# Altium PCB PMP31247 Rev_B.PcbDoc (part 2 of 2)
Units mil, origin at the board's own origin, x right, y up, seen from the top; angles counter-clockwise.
Board outline 3522.83 x 1490.94 mil, 4 copper layers (Top Layer, GND Plane, Signal Layer, Bottom Layer), stack 70.4 mil thick; 56 components, 24 nets, 121 pads, 112 vias.
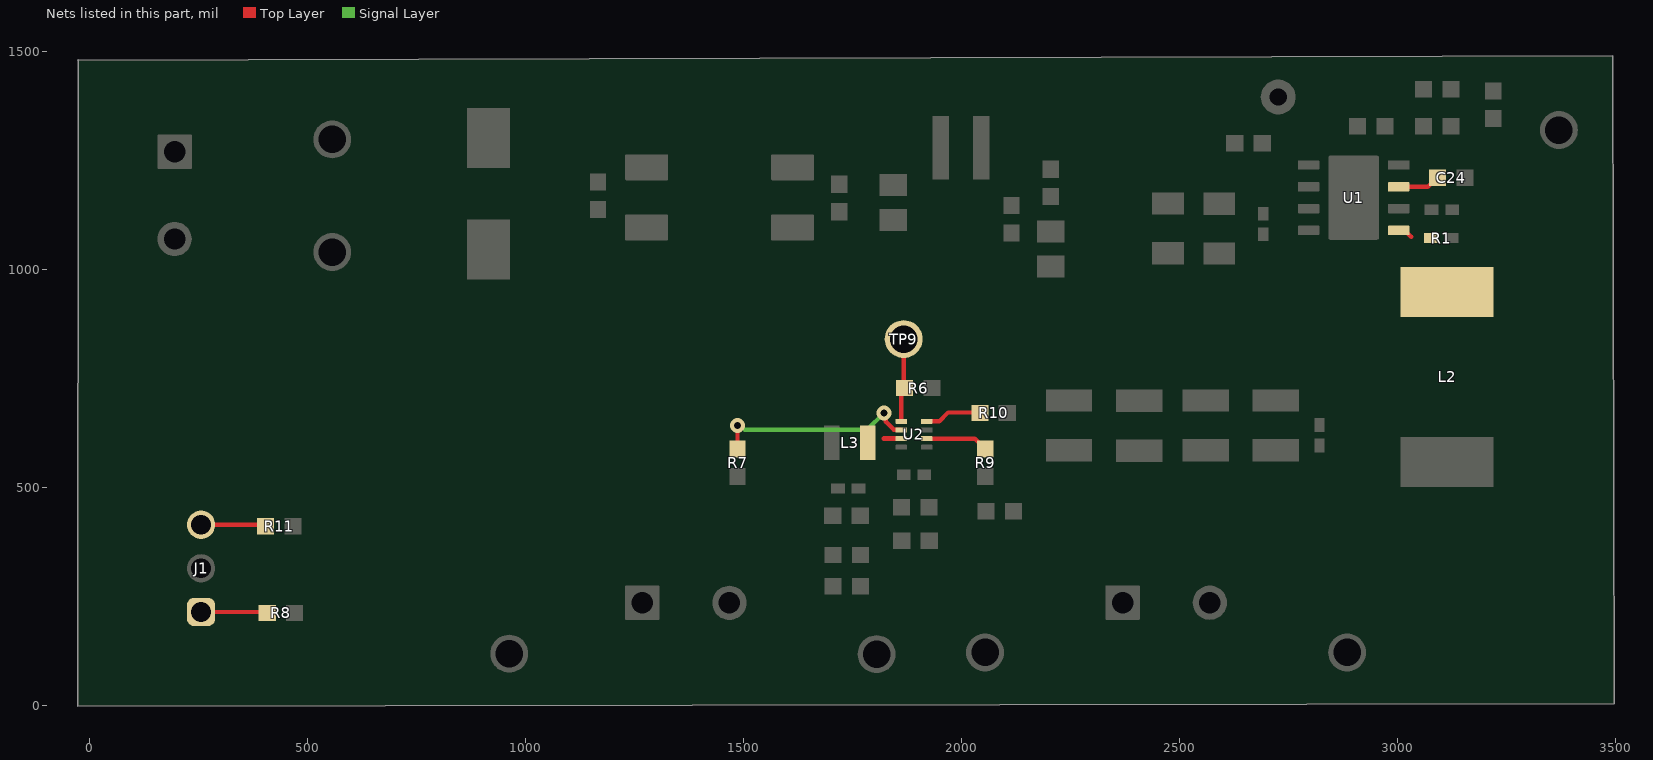
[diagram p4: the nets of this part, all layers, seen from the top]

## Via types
v1: diameter 34, hole 16, Top Layer to Bottom Layer, tented both sides, 104 vias
v2: diameter 19.68, hole 7.87, Top Layer to Bottom Layer, 4 vias
v3: diameter 19.68, hole 7.87, Top Layer to Bottom Layer, tented both sides, 4 vias

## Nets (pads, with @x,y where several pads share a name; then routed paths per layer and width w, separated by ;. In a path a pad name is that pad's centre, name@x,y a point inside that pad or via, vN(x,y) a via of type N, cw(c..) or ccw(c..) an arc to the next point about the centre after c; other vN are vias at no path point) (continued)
NetJ1_1: J1.1 R8.1 | length 166.9
  Top Layer w10: J1.1@255.91,214.96 R8.1@405.51,214.96 ; R8.1@395.28,212.2 R8.1@407.48,224.41
NetJ1_3: J1.3 R11.2 | length 143.3
  Top Layer w10: J1.3@255.91,414.96 R11.2@399.21,414.96
NetL2_1: L2.1 R1.1 U1.1 | length 141.2
  Top Layer w10: U1.1@3001.97,1089.76 3015.75,1089.76 3030.71,1074.8 ; L2.1@3032.08,1000.91 3084.17,948.82 L2.1@3112.79,948.82 ; R1.1@3071.85,1072.27 R1.1@3075.79,1072.27
NetL3_1: L3.1 U2.7 | length 45.6
  Top Layer w10: L3.1@1792.38,623.42 L3.1@1796.4,619.41 ; 1821.49,612.35 1821.59,612.44
  Top Layer w11.81: 1821.59,612.44 U2.7@1861.42,612.44
NetR6_1: R6.1 TP9.1 U2.5 | length 179.7
  Top Layer w10: U2.5@1861.42,651.81 R6.1@1861.42,718.5 ; TP9.1@1866.96,840.55 1866.96,730.28 R6.1@1868.9,728.35
NetR7_1: R7.1 U2.6 | length 474.3
  Top Layer w10: R7.1@1486.02,588.8 v1(1486.02,642.31) ; v1(1821.59,671.26) 1826.18,666.67 1826.18,650.89 1844.04,633.03 1860.51,633.03 U2.6@1861.42,632.13
  Signal Layer w10: v1(1486.02,642.31) 1492.52,642.31 1502.16,632.68 1783,632.68 v1(1821.59,671.26)
NetR9_2: R9.2 U2.2 | length 144.7
  Top Layer w10: U2.2@1919.69,612.44 2030.08,612.44 2039.25,603.27 2040.24,603.27 2053.94,589.57 R9.2@2053.94,588.58
NetR10_2: R10.2 U2.4 | length 130.7
  Top Layer w10: U2.4@1919.69,651.81 1948.35,651.81 1968.73,672.19 2040.61,672.19 R10.2@2041.54,671.26
VCC: C24.1 U1.3 | length 97.2
  Top Layer w10: U1.3@3001.97,1189.76 3002.17,1189.96 3068.9,1189.96 3089.57,1210.63 C24.1@3090.55,1210.63
pads on no net: U1.9@2898.62,1164.76

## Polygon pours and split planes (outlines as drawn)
GND on Top Layer "GND_L01_P058" (solid, remove dead copper, pour order 63): 1.97,774.8 3643.7,774.8 3643.7,-395.67 3639.76,-391.73 1.97,-391.73
NetC2_1 on Top Layer "NETC2_1_L01_P066" (solid, remove dead copper, pour order 66): 2024.82,1204.72 2024.82,1353.54 2024.94,1353.66 2065.9,1353.66 2065.9,1353.41 2104.91,1314.4 2104.91,1204.72
NetC6_1 on Top Layer "NETC6_1_L01_P065" (solid, remove dead copper, pour order 65): 1971.65,1204.72 1971.65,1353.54 1971.54,1353.66 1930.58,1353.66 1930.58,1353.41 1895.67,1318.5 1895.67,1204.72
NetC14_1 on Top Layer "NETC14_1_L01_P040" (solid, remove dead copper, pour order 40): 2075.34,464.41 2074.81,464.94 1970.89,464.94 1937.8,498.03 1894.01,498.03 1894.01,356.78 1894.49,356.3 1894.5,356.31 1965.08,356.31 2035.93,427.17 2075.56,427.17
NetL3_1 on Top Layer "NETL3_1_L01_P046" (solid, remove dead copper, pour order 46): 1835.53,615.97 1835.53,606.77 ccw(c1835.53,591.58) 1824.79,602.32 1801.84,563.95 1767.98,582.75 1767.98,616.53
NetL3_1 on Top Layer "NETL3_1_L01_P064" (solid, remove dead copper, pour order 64): 1834.28,609.05 1834.28,618.25 cw(c1834.27,633.44) 1823.54,622.7 1801.93,642.63 1766.73,641.02 1766.73,608.48
NetL2_1 on Top Layer "NETL2_1_L01_P049" (solid, remove dead copper, pour order 49): 2977.49,1101.41 3081.37,1101.41 cw(c3074.22,1080.95) 3093.74,1090.36 3093.74,1018.76 ccw(c3119.99,1045) 3119.99,1007.88 3212.65,1007.88 cw(c3212.65,993.39) 3222.89,1003.64 cw(c3220.37,1001.12) 3223.94,1001.12 3223.94,894.69 cw(c3215.19,894.68) 3221.38,888.5 3218.5,885.63 cw(c3211.29,892.84) 3211.29,882.64 3020.61,882.64 cw(c3020.61,906.92) 3003.44,889.75 cw(c3007.01,893.32) 3001.97,893.32 3001.97,1069.33 ccw(c2980.58,1047.4) 2981.67,1078.01 2977.49,1078.01
NetC2_1 on Top Layer "NETC2_1_L01_P050" (solid, remove dead copper, pour order 50): 2071.3,1319.88 2297.28,1319.88 2407.27,1209.9 2712.85,1209.9 2773.5,1149.25 2817.93,1149.25 2817.93,1127.95 2812.97,1122.99 2344.4,1122.99 2257.49,1209.9 2071.3,1209.9
GNDA on Top Layer "GNDA_L01_P051" (solid, remove dead copper, pour order 51): 1326.77,1125.98 1326.77,1066.93 1153.15,893.31 17.32,893.31 17.32,1125.98
NetC5_1 on Top Layer "NETC5_1_L01_P052" (solid, remove dead copper, pour order 52): 1326.77,1204.72 1326.77,1263.78 1137.8,1452.76 16.14,1452.76 16.14,1204.72
3V3 on Top Layer "3V3_L01_P053" (solid, remove dead copper, pour order 53): 2184.29,616.14 3188.98,616.14 3188.98,498.03 2791.34,498.03 2720.47,427.17 2184.29,427.17
NetC14_1 on Top Layer "NETC14_1_L01_P054" (solid, remove dead copper, pour order 54): 1937.8,356.3 1937.8,600.39 1906.3,600.39 1906.3,549.21 1894.49,537.4 1894.49,356.3
Net1.2V_1 on Top Layer "NET1.2V_1_L01_P055" (solid, remove dead copper, pour order 55): 1735.7,642.31 1735.7,258.53 1595.28,118.11 1376.77,118.11 1376.77,390 1539.49,390 1683.97,534.48 1683.97,642.31
3V3 on Top Layer "3V3_L01_P056" (solid, remove dead copper, pour order 56): 2272.44,444.91 2272.44,161.42 2278.35,155.51 2473.23,155.51 2473.23,425.43 2477.17,444.91
GND on Top Layer "GND_L01_P057" (solid, remove dead copper, pour order 57): 1562.99,1126.38 1564.54,1124.83 1726.62,1124.83 1726.62,1068.08 1561.02,1068.08
GND on Top Layer "GND_L01_P058" (solid, remove dead copper, pour order 58): 1563.64,1124.83 1753.28,1124.83 1775.91,1102.2 2116.93,1102.2 2116.93,1090.36 2173.83,1033.46 2246.06,1033.46 2322.83,1033.46 2322.83,907.48 2114.89,907.48 2049.93,972.44 1731.3,972.44 1577.27,1070.11
NetC6_1 on Top Layer "NETC6_1_L01_P059" (solid, remove dead copper, pour order 59): 1567.87,1204.72 1925.57,1204.72 1925.57,1319.88 1652.95,1319.88 1597.96,1264.89 1567.87,1264.89
GND on Top Layer "GND_L01_P061" (solid, remove dead copper, pour order 61): 2316.93,1623.36 2316.93,676.91 3638.05,676.91 3643.7,671.26 3643.7,1631.89
GND on GND Plane "GND_L02_P021" (solid, remove dead copper, pour order 21): 2316.93,1623.36 2316.93,676.91 3638.05,676.91 3643.7,671.26 3643.7,1631.89
GND on GND Plane "GND_L02_P020" (solid, remove dead copper, pour order 20): 2.79,775.1 3644.53,775.1 3644.53,-394.85 3640.59,-390.91 2.79,-390.91
GND on Signal Layer "GND_L03_P027" (solid, remove dead copper, pour order 27): 2316.93,1615.48 2316.93,669.04 3638.05,669.04 3643.7,663.39 3643.7,1624.02
GND on Signal Layer "GND_L03_P028" (solid, remove dead copper, pour order 28): 0.32,775.1 3642.06,775.1 3642.06,-395.67 3638.12,-391.73 0.32,-391.73
GND on Bottom Layer "GND_L04_P030" (solid, remove dead copper, pour order 30): 1.97,775.1 3643.7,775.1 3643.7,-395.67 3639.76,-391.73 1.97,-391.73
GND on Bottom Layer "GND_L04_P029" (solid, remove dead copper, pour order 29): 2316.93,1623.36 2316.93,676.91 3638.05,676.91 3643.7,671.26 3643.7,1631.89

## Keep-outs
Keep-Out Layer:
  text ".Layer_Name" at 572.5,-1392.79 h60

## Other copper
Top Layer:
  pour cut-out: -5.17,770.02 -7.48,767.72 -7.48,512.99 1273.62,512.99 1535.43,774.8
  text ".Layer_Name" at 493.76,-1392.79 h60
GND Plane:
  pour cut-out: -7.48,770.31 -7.48,513.29 1273.37,513.29 1535.18,775.1
  text ".Layer_Name" at 572.5,-1394.76 h60
Signal Layer:
  pour cut-out: 13.13,770.38 -3.15,754.09 -3.15,513.29 1273.76,513.29 1535.57,775.1
  text ".Layer_Name" at 573.29,-1392.79 h60
Bottom Layer:
  pour cut-out: 13.13,770.38 -0.79,756.46 -0.79,513.29 1273.76,513.29 1535.57,775.1
  text ".Layer_Name" at 572.5,-1392.79 h60

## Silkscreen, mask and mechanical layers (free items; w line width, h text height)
Top Overlay:
  text "GND" at 142.22,903.64 h30
  text "'.PRJ_Number' Rev_B" at 272.05,580.31 h108.27
  text "PFM" at 72.93,397.34 h30
  text "SYNC" at 69.39,301.28 h30
  text "FPWM" at 73.32,198.91 h30
  text ".Layer_Name" at 572.5,-1392.79 h60
Bottom Overlay:
  text ".Layer_Name" at 572.5,-1392.79 h60
Top Paste:
  text ".Layer_Name" at 572.5,-1392.79 h60
Bottom Paste:
  text ".Layer_Name" at 572.5,-1392.79 h60
Top Solder:
  text ".Layer_Name" at 572.5,-1392.79 h60
  text ".Layer_Name" at 572.5,-1392.79 h60
Bottom Solder:
  text ".Layer_Name" at 572.5,-1392.79 h60
Drill Guide:
  text ".Layer_Name" at 572.5,-1392.79 h60
M1 Board Outline:
  lines w10: -27.17,-0.39 3496.06,3.94 3492.13,1490.16 -26.77,1479.92 ; -26.77,-0.79 -25.98,1481.5
  text ".Layer_Name" at 493.76,-1392.79 h60
M2 Board Dimensions:
  rectangle: 120.5,-934.3 495.5,-809.3
  rectangle: -4.5,-809.3 120.5,-684.3
  lines w7: -4.5,-809.3 995.5,-809.3 ; 120.5,-934.3 120.5,-684.3 ; 245.5,-934.3 245.5,-684.3 ; 495.5,-934.3 495.5,-684.3 ; 745.5,-934.3 745.5,-684.3 ; -4.5,-934.3 -4.5,-684.3 995.5,-684.3 995.5,-934.3 -4.5,-934.3
  text "PMP31247" at 1439.41,1535.87 h100
  text ".Layer_Name" at 493.76,-1392.79 h60
M3 3D STEP Top:
  text ".Layer_Name" at 493.76,-1392.79 h60
M4 3D STEP Bottom:
  text ".Layer_Name" at 493.76,-1392.79 h60
M5 Assembly Top:
  lines w10: -316.19,-1464.46 5533.85,-1464.46 ; -316.19,-1261.13 5533.85,-1261.13 ; -316.19,-1057.8 -316.19,-1667.8 3688.81,-1667.8 ; 1259.82,-1667.8 -315.69,-1667.8 -315.69,-1057.8 5533.85,-1057.8 5533.85,-1667.8 3212.44,-1667.8 ; 1967.71,-1667.8 1967.71,-1057.8 ; 2998.49,-1261.13 2998.49,-1057.8 ; 3720.38,-1261.13 3720.38,-1057.8 ; 4224.27,-1674.3 4224.27,-1471.46
  text "COMPONENTS MARKED 'DNP' SHOULD NOT BE POPULATED." at 1026.95,-852.8 h60
  text "ASSEMBLY VARIANT:" at 1026.45,-968.3 h60
  text ".VariantName" at 2054.58,-968.3 h60
  text "PCB VIEWED FROM TOP SIDE" at -272.37,-1189.96 h60
  text "BOARD #:" at 2011.22,-1189.96 h60
  text ".PRJ_Number" at 2470.1,-1189.96 h60
  text "REV:" at 3157.12,-1189.96 h60
  text ".PCB_Rev" at 3389.57,-1189.96 h60
  text "SVN REV:" at 3790.4,-1189.96 h60
  text ".VersionControl_RevNumber" at 4284.59,-1189.96 h60
  text "TID #:" at 2011.22,-1393.3 h60
  text ".TID" at 2470.1,-1393.3 h60
  text "PLOT NAME =" at -272.37,-1598.63 h60
  text ".plot_File_Name" at 493.76,-1598.63 h60
  text "GENERATED    :" at 2013.22,-1598.63 h60
  text ".Print_Date" at 2737.05,-1598.63 h60
  text ".Print_Time" at 3328.25,-1598.63 h60
  text "TEXAS INSTRUMENTS" at 4395.9,-1598.63 h60
M6 Assembly Bottom:
  lines w10: -316.69,-1261.63 5533.85,-1261.63 ; -314.69,-1464.96 5533.85,-1464.96 ; 1008.64,-1674.8 1008.64,-1471.96 ; 1551.9,-1261.63 1551.9,-1058.3 ; 2040.16,-1668.3 5533.85,-1668.3 4075.46,-1668.3 ; 2280.32,-1668.3 -316.69,-1668.3 -316.69,-1058.3 5533.85,-1058.3 ; 2293.47,-1261.63 2293.47,-1058.3 ; 3324.25,-1668.3 3324.25,-1058.3 ; 5532.85,-1668.3 5532.85,-1058.3 ; 5533.35,-1668.3 5533.35,-1058.3
  text "COMPONENTS MARKED 'DNP' SHOULD NOT BE POPULATED." at 5699.86,-852.3 h60
  text ".VariantName" at 4360.59,-968.3 h60
  text "ASSEMBLY VARIANT:" at 5360.22,-968.3 h60
  text ".VersionControl_RevNumber" at 1031,-1190.46 h60
  text "SVN REV:" at 1517.32,-1190.46 h60
  text ".PCB_Rev" at 1922.08,-1190.46 h60
  text "REV:" at 2162.4,-1190.46 h60
  text ".PRJ_Number" at 2762.81,-1190.46 h60
  text "BOARD #:" at 3229.57,-1190.46 h60
  text "PCB VIEWED FROM BOTTOM SIDE" at 5489.53,-1190.46 h60
  text ".TID" at 2782.49,-1393.8 h60
  text "TID #:" at 3229.57,-1393.8 h60
  text "TEXAS INSTRUMENTS" at 840.94,-1599.13 h60
  text ".Print_Time" at 2022.77,-1599.13 h60
  text ".Print_Date" at 2641.53,-1599.13 h60
  text "GENERATED    :" at 3424.42,-1599.13 h60
  text ".plot_File_Name" at 4821.83,-1599.13 h60
  text "PLOT NAME =" at 5489.53,-1599.13 h60
M9 Title Sheet:
  drawing of 55 lines, arcs and shapes, not listed
  text "1" at 656.34,4797.2 h70
  text "2" at 3014.35,4797.2 h70
  text "3" at 5391,4797.2 h70
  text "4" at 7766.35,4797.2 h70
  text "A" at -441,3907.2 h70
  text "A" at 8854,3907.2 h70
  text "B" at -441,2031.2 h70
  text "B" at 8854,2031.2 h70
  text "C" at -441,155.2 h70
  text "C" at 8854,155.2 h70
  text "PROJECT TITLE:" at 5819,-956.8 h45
  text ".PRJ_Title" at 5869,-1090.12 h70
  text "DESIGNED FOR:" at 5819,-1257.8 h45
  text ".PRJ_Customer" at 5869,-1397.8 h70
  text "FILE NAME:" at 5819,-1557.8 h45
  text ".PCB_File_Name_No_Path" at 5869,-1677.8 h70
  text "D" at -441,-1716.8 h70
  text "D" at 8854,-1716.8 h70
  text "Texas Instruments (TI) and/or its licensors do not warrant the accuracy or completeness of this specification" at 959.5,-1839.63 h45
  text "ENGINEER:" at 5819,-1847.8 h45
  text "LAYOUT BY:" at 7324,-1847.8 h45
  text "or any information contained therein. TI and/or its licensors do not warrant that this design will meet" at 914.51,-1952.3 h45
  text ".PRJ_Engineer" at 5869,-2002.79 h70
  text ".PCB_Layout" at 7374.5,-2002.79 h70
  text "the specifications, will be suitable for your application or fit for any particular purpose, or will operate in" at 914.51,-2064.96 h45
  text "ALTIUM DESIGNER VERSION:" at 7324,-2157.8 h45
  text "an implementation. TI and/or its licensors do not warrant that the design is production worthy. You should" at 914.51,-2177.63 h45
  text "completely validate and test your design implementation to confirm the system functionality for your application." at 959.5,-2290.3 h40
  text ".print_Scale" at 5869,-2291.12 h70
  text ".Application_BuildNumber" at 7374.5,-2291.12 h70
  text "1" at 656.34,-2502.8 h70
  text "2" at 3014.35,-2502.8 h70
  text "3" at 5391,-2502.8 h70
  text "4" at 7766.35,-2502.8 h70
M10 Fab Notes:
  drawing of 189 lines, arcs and shapes, not listed
  text "DESIGN INFORMATION" at 6855.02,4627.38 h60
  text "MIN. TRACK WIDTH:" at 6210.46,4495.25 h60
  text "10" at 7306.7,4495.26 h60
  text "MIL" at 7461.46,4495.25 h60
  text "7.874" at 7135.83,4375.98 h60
  text "MIN. CLEARANCE:" at 6210.46,4371.13 h60
  text "MIL" at 7461.46,4371.13 h60
  text "MIN. VIA PAD SIZE:" at 6210.46,4247 h60
  text "24" at 7276.71,4247 h60
  text "MIL" at 7461.46,4247 h60
  text "0.05mm (2MIL)" at 6905.46,4117.1 h60
  text "MINIMUM ANNULAR RING" at 5881.23,4108.88 h60
  text "EXTERNAL" at 7613.46,4108.88 h60
  text "PER" at 6081.23,3998.75 h60
  text "IPC-D-275 CLASS 2 LEVEL C" at 6301.23,3998.75 h60
  text "MIL, HOLES" at 7789.46,3898.27 h60
  text "+/-" at 7397,3889.69 h60
  text "+/-" at 8251,3889.69 h60
  text "REGISTRATION TOLERANCES:" at 5881.23,3888.62 h60
  text "METAL" at 7081,3888.62 h60
  text "5" at 7657.2,3888.63 h60
  text "3" at 8490.2,3888.63 h60
  text "MIL" at 8606.46,3888.62 h60
  text "HOLE SIZE TOLERANCE (UNLESS OTHERWISE SPECIFIED):" at 5881.23,3790.31 h60
  text "+/-" at 8251,3787.44 h60
  text "3" at 8490.2,3786.37 h60
  text "MIL" at 8606.46,3786.37 h60
  text "MATERIAL:" at 5806.46,3648.72 h60
  text "FR-4 High Tg" at 6792.9,3520.2 h60
  text "X" at 6648.46,3512.21 h60
  text "FR-4" at 6227.46,3507.69 h60
  text "OTHER" at 7715.46,3507.69 h60
  text "62 MIL (1.6mm) +/-10%" at 6547.56,3364.66 h60
  text "X" at 6427.46,3362.21 h60
  text "THICKNESS:" at 5881.23,3356.44 h60
  text "OTHER" at 7832.46,3356.44 h60
  text "TOLERANCE:" at 5881.23,3218.13 h60
  text "X" at 6729.46,3218.13 h60
  text "ANSI IPC-6012 TYPE 3 CLASS 2" at 6907.48,3218.13 h60
  text "OTHER +/-" at 6907.46,3073.94 h60
  text "BOW & TWIST:" at 5881.23,2928.75 h60
  text "X" at 6729.46,2928.75 h60
  text "ANSI IPC-6012 TYPE 3 CLASS 2" at 6907.48,2928.75 h60
  text "OTHER +/-" at 6907.46,2782.05 h60
  text "DRILLING:" at 5806.46,2651.43 h60
  text "NC_DRILL FILES" at 7567.46,2546.25 h60
  text "REFERENCE:" at 5881.23,2542.31 h60
  text "X" at 6538.46,2542.21 h60
  text "AS SHOWN" at 6716.46,2542.31 h60
  text "X" at 7439.46,2542.31 h60
  text "OTHER" at 7865.46,2400.06 h60
  text "PTH COPPER THICKNESS:" at 5880.91,2396.53 h60
  text "X" at 7020.14,2396.53 h60
  text "20-30 um" at 7148.14,2396.53 h60
  text "BOARD FINISH:" at 5806.46,2248.93 h60
  text "SILKSCREEN:" at 5961.68,2138.8 h60
  text "X" at 6919.46,2138.8 h60
  text "TOP" at 7036.46,2138.8 h60
  text "X" at 7429.46,2138.8 h60
  text "BOTTOM" at 7547.46,2138.8 h60
  text "SILKSCREEN COLOR:" at 5961.68,1983.62 h60
  text "X" at 6918.46,1983.62 h60
  text "WHITE" at 7036.46,1983.62 h60
  text "OTHER" at 7547.46,1983.62 h60
  text "X" at 7049.46,1840.17 h60
  text "GREEN" at 7167.46,1840.17 h60
  text "OTHER" at 7785.46,1840.17 h60
  text "SOLDER RESIST COLOR:" at 5961.68,1833.3 h60
  text "X" at 7049.46,1685.91 h60
  text "MATTE" at 7167.46,1685.91 h60
  text "SEMI-GLOSS" at 7785,1685.28 h60
  text "IMMERSION GOLD (ENIG)" at 6867.46,1513.14 h60
  text "ENEPIG" at 8205,1505.92 h60
  text "SURFACE FINISH:" at 5806.46,1504.92 h60
  text "X" at 7387.4,1374.8 h60
  text "IMM. TIN/SILVER OR EQUIV" at 6136,1367.61 h60
  text "OTHER" at 7567.46,1363.67 h60
  text "ARRAY/PANEL:" at 5806.46,1208.29 h60
  text "CUT AND TRIM PER M1 BOARD OUTLINE" at 6867.46,1200.07 h60
  text "N.C. ROUTE" at 6867.46,1064.1 h60
  text "X" at 7555.46,1064.1 h60
  text "V. SCORE" at 7733.46,1064.1 h60
  text "CERTIFICATION:" at 5806.46,934.98 h60
  text "MATERIALS AND WORKMANSHIP FOR ALL PCBS" at 6531.46,934.98 h60
  text "TO MEET OR EXCEED THE REQUIREMENTS OF:" at 6531.46,840.91 h60
  text "X" at 6168.97,712.28 h60
  text "ANSI IPC-A-600F CLASS ->" at 6296.96,712.28 h60
  text "X" at 7944.97,712.28 h60
  text "2" at 8054.96,712.28 h60
  text "1" at 7739.96,710.79 h60
  text "3" at 8408.96,710.79 h60
  text "X" at 6980.97,564.6 h60
  text "RoHS" at 7108.96,564.6 h60
  text "OTHER" at 7753.36,564.6 h60
  text "PER ORDER" at 8150.42,564.6 h60
  text "ALL BOARDS MUST MEET OR EXCEED UL94-V0 REQUIREMENTS." at 5834,410.77 h60
  text "PCB MUST BEAR THE UL94V-0 UL REGISTERED MATERIAL ID NUMBER" at 5834,294.71 h60
  text "ADDITIONAL REQUIREMENTS:" at 5806.46,125.28 h60
  text "MICROSECTION:" at 5881.23,18.16 h60
  text "YES" at 6786.96,18.16 h60
  text "REQUIRED" at 7648.46,-126.17 h60
  text "BARE BOARD ELEC. TEST:" at 5881.23,-129.03 h60
  text "NONE" at 7186.96,-129.03 h60
  text "PER ORDER" at 8240.46,-129.03 h60
  text "X" at 7074.8,-133.86 h60
  text "XX MIL VIAS REQUIRE NON-CONDUCTIVE FILL AND PLANARIZE" at 6049.38,-333.98 h59
  text "XX MIL VIAS REQUIRE CONDUCTIVE FILL AND PLANARIZE" at 6057.38,-437.95 h60
  text "OUTER XX MIL TRACES REQUIRE 50 OHM SINGLE-ENDED IMPEDANCE" at 6056.39,-601.34 h58
  text "LAYER 2 & 3 (INNER LAYERS) XX MIL WIDE, XX MIL SPACE / TRACES REQUIRE 100 OHM DIFFERENTIAL IMPEDANCE" at 6048.39,-837.05 h60
  text ".Layer_Name" at 493.76,-1392.79 h60
M11 Gerber Information:
  lines w10: -316.19,-1464.46 5533.85,-1464.46 ; -316.19,-1261.13 5533.85,-1261.13 ; -316.19,-1057.8 -316.19,-1667.8 3688.81,-1667.8 ; 1259.82,-1667.8 -315.69,-1667.8 -315.69,-1057.8 5533.85,-1057.8 5533.85,-1667.8 3212.44,-1667.8 ; 1967.71,-1667.8 1967.71,-1057.8 ; 2998.49,-1261.13 2998.49,-1057.8 ; 3720.38,-1261.13 3720.38,-1057.8 ; 4224.27,-1674.3 4224.27,-1471.46
  text "ALL ARTWORK VIEWED FROM TOP SIDE" at -272.37,-1189.96 h60
  text "BOARD #:" at 2011.22,-1189.96 h60
  text ".PRJ_Number" at 2470.1,-1189.96 h60
  text "REV:" at 3157.12,-1189.96 h60
  text ".PCB_Rev" at 3389.57,-1189.96 h60
  text "SVN REV:" at 3790.4,-1189.96 h60
  text ".VersionControl_RevNumber" at 4284.59,-1189.96 h60
  text "LAYER NAME =" at -272.37,-1392.79 h60
  text "TID #:" at 2011.22,-1393.3 h60
  text ".TID" at 2470.1,-1393.3 h60
  text "PLOT NAME =" at -272.37,-1598.63 h60
  text ".plot_File_Name" at 493.76,-1598.63 h60
  text "GENERATED    :" at 2013.22,-1598.63 h60
  text ".Print_Date" at 2737.05,-1598.63 h60
  text ".Print_Time" at 3328.25,-1598.63 h60
  text "TEXAS INSTRUMENTS" at 4395.9,-1598.63 h60
M12 Stackup:
  drawing of 295 lines, arcs and shapes, not listed
  text "Layer" at 202.84,4429.45 h60
  text "Name" at 612.76,4429.45 h60
  text "Material" at 1542.5,4429.45 h60
  text "Thickness" at 2402.27,4429.45 h60
  text "Constant" at 3052.1,4429.45 h60
  text "Board Layer Stack" at 3621.96,4429.45 h60
  text "Top Overlay" at 612.76,4309.45 h60
  text "Top Solder" at 612.76,4189.45 h60
  text "Solder Resist" at 1542.5,4189.45 h60
  text "0.40mil" at 2402.27,4189.45 h60
  text "3.5" at 3052.1,4189.45 h60
  text "1" at 202.84,4069.45 h60
  text "Top Layer" at 612.76,4069.45 h60
  text "1.40mil" at 2402.27,4069.45 h60
  text "Dielectric 1" at 612.76,3949.45 h60
  text "PP-006" at 1542.5,3949.45 h60
  text "2.80mil" at 2402.27,3949.45 h60
  text "4.1" at 3052.1,3949.45 h60
  text "2" at 202.84,3829.45 h60
  text "GND Plane" at 612.76,3829.45 h60
  text "CF-004" at 1542.5,3829.45 h60
  text "1.40mil" at 2402.27,3829.45 h60
  text "Dielectric1" at 612.76,3709.45 h60
  text "FR-4 High Tg" at 1542.5,3709.45 h60
  text "59.20mil" at 2402.27,3709.45 h60
  text "4.8" at 3052.1,3709.45 h60
  text "3" at 202.84,3589.45 h60
  text "Signal Layer" at 612.76,3589.45 h60
  text "CF-004" at 1542.5,3589.45 h60
  text "1.40mil" at 2402.27,3589.45 h60
  text "Dielectric 2" at 612.76,3469.45 h60
  text "PP-006" at 1542.5,3469.45 h60
  text "2.80mil" at 2402.27,3469.45 h60
  text "4.1" at 3052.1,3469.45 h60
  text "4" at 202.84,3349.45 h60
  text "Bottom Layer" at 612.76,3349.45 h60
  text "1.40mil" at 2402.27,3349.45 h60
  text "Bottom Solder" at 612.76,3229.45 h60
  text "Solder Resist" at 1542.5,3229.45 h60
  text "0.40mil" at 2402.27,3229.45 h60
  text "3.5" at 3052.1,3229.45 h60
  text "Bottom Overlay" at 612.76,3109.45 h60
  text ".Layer_Name" at 493.76,-1392.79 h60
M13 Component Bodies Top:
  text ".Layer_Name" at 493.76,-1392.79 h60
M14 Component Bodies Bottom:
  text ".Layer_Name" at 493.76,-1392.79 h60
M15 Courtyards Top:
  text ".Layer_Name" at 493.76,-1392.79 h60
M16 Courtyards Bottom:
  text ".Layer_Name" at 493.76,-1392.79 h60
Drill Drawing:
  circle w10: c403.94,2008.01 r27.67
  lines w10: 376.27,2160.18 431.6,2160.18 403.94,2104.85 376.27,2160.18 ; 376.27,2243.18 390.1,2243.18 403.94,2229.35 417.77,2243.18 431.6,2243.18 417.77,2257.01 431.6,2270.85 417.77,2270.85 403.94,2284.68 390.1,2270.85 376.27,2270.85 390.1,2257.01 376.27,2243.18 ; 376.27,2367.68 390.1,2367.68 390.1,2353.85 417.77,2353.85 417.77,2367.68 431.6,2367.68 431.6,2395.35 417.77,2395.35 417.77,2409.18 390.1,2409.18 390.1,2395.35 376.27,2395.35 376.27,2367.68 ; 376.27,2478.35 431.6,2478.35 431.6,2533.68 376.27,2533.68 376.27,2478.35 ; 376.27,2602.85 403.94,2616.68 431.6,2602.85 417.77,2630.51 431.6,2658.18 403.94,2644.35 376.27,2658.18 390.1,2630.51 376.27,2602.85
  lines w12: 326.11,1943 3452.36,1943 ; 326.11,2690 3452.36,2690 ; 664.12,1818.5 664.12,2814.5 ; 963.57,1818.5 963.57,2814.5 ; 1526.82,1818.5 1526.82,2814.5 ; 1786.02,1818.5 1786.02,2814.5 ; 2161.26,1818.5 2161.26,2814.5 ; 2885.81,1818.5 2885.81,2814.5 ; 326.11,1818.5 3452.36,1818.5 3452.36,2814.5 326.11,2814.5 326.11,1818.5
  text "Symbol" at 400.81,2727.35 h72
  text "Count" at 701.47,2727.35 h72
  text "Hole Size" at 1000.92,2727.35 h72
  text "Plated" at 1564.17,2727.35 h72
  text "Hole Type" at 1823.37,2727.35 h72
  text "Drill Layer Pair" at 2198.61,2727.35 h72
  text "Hole Tolerance" at 2923.16,2727.35 h72
  text "8" at 701.47,2602.85 h60
  text "7.87mil (0.200mm)" at 1000.92,2602.85 h60
  text "PTH" at 1564.17,2602.85 h60
  text "Round" at 1823.37,2602.85 h60
  text "Top Layer - Bottom Layer" at 2198.61,2602.85 h60
  text "104" at 701.47,2478.35 h60
  text "16.00mil (0.406mm)" at 1000.92,2478.35 h60
  text "PTH" at 1564.17,2478.35 h60
  text "Round" at 1823.37,2478.35 h60
  text "Top Layer - Bottom Layer" at 2198.61,2478.35 h60
  text "1" at 701.47,2353.85 h60
  text "40.00mil (1.016mm)" at 1000.92,2353.85 h60
  text "PTH" at 1564.17,2353.85 h60
  text "Round" at 1823.37,2353.85 h60
  text "Top Layer - Bottom Layer" at 2198.61,2353.85 h60
  text "3" at 701.47,2229.35 h60
  text "45.28mil (1.150mm)" at 1000.92,2229.35 h60
  text "PTH" at 1564.17,2229.35 h60
  text "Round" at 1823.37,2229.35 h60
  text "Top Layer - Bottom Layer" at 2198.61,2229.35 h60
  text "6" at 701.47,2104.85 h60
  text "49.21mil (1.250mm)" at 1000.92,2104.85 h60
  text "PTH" at 1564.17,2104.85 h60
  text "Round" at 1823.37,2104.85 h60
  text "Top Layer - Bottom Layer" at 2198.61,2104.85 h60
  text "8" at 701.47,1980.35 h60
  text "63.00mil (1.600mm)" at 1000.92,1980.35 h60
  text "PTH" at 1564.17,1980.35 h60
  text "Round" at 1823.37,1980.35 h60
  text "Top Layer - Bottom Layer" at 2198.61,1980.35 h60
  text "130 Total" at 701.47,1855.85 h60
  text ".Layer_Name" at 493.76,-1392.79 h60
M17 Embedded Cavity:
  text ".Layer_Name" at 493.76,-1392.79 h60
M18 Embedded Assembly:
  text ".Layer_Name" at 493.76,-1392.79 h60
M19 Embedded Keepout:
  text ".Layer_Name" at 497.7,-1396.73 h60

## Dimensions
-27.17,-0.39 to -26.77,1479.92 on M2 Board Dimensions
-26.77,-0.79 to 3496.06,3.94 on M2 Board Dimensions
-4.5,-934.3 to 995.5,-934.3 on M2 Board Dimensions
